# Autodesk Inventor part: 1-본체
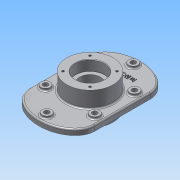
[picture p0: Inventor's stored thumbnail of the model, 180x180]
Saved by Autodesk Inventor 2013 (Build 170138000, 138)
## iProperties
Created: 2015-02
Part Number: 1-본체
Material: 알루미늄 6061
Document SubType Name: Modeling
Designer: Administrator
Mass: 1662.1 g
Surface Area: 942.609 cm^2
Volume: 613.321 cm^3
Density: 2.71 g/cm^3
Author: Administrator
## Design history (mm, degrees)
sketch "스케치1"
  geometry: L1 (70, 60)-(-70, 60); L2 (-70, 60)-(-70, -60); L3 (-70, -60)-(70, -60); L4 (70, -60)-(70, 60); L5 (70, 60)-(-70, -60); L6 (-70, 60)-(70, -60); 7 further points; 2 other entities
  constraints: 12 end point, 6 midpoint, 3 horizontal, 2 parallel, 2 vertical alignment, 1 perpendicular, 8 other
  dimensions: "d0" = 140 distance of L1.start L1.end; "d2" = 120 distance of L3.end L1.start; "d3" = 50 distance from line of L1 point (0, 110); "d4" = 50 distance from line of point (0, -110) L3
extrude "돌출1" new body sketch "스케치1" distance "d5" = 12; taper "d6" = 0 deg
sketch "스케치3"
  geometry: L1 (70, -60)-(70, 60) reference; L2 (-70, 60)-(-70, -60) reference; L3 (53, 60)-(53, -60); L4 (-53, -60)-(-53, 60); C1 r 10 at (53, 42.733); C2 r 10 at (53, -42.733); C3 r 10 at (0, 93); C4 r 10 at (0, -93); C5 r 10 at (-53, 42.733); C6 r 10 at (-53, -42.733); 3 further points; 2 other entities
  constraints: 6 centre point, 5 equal radius, 4 end point, 4 point on line, 3 parallel, 2 vertical alignment, 10 other
  dimensions: "d32" = 17 distance between parallel lines of L1 L3; "d33" = 20 diameter of C1; "d34" = 85.46667 distance of C2.centre C1.centre; "d35" = 42.73333 vertical distance of C2.centre point (0, 0); "d74" = 85.46667 distance of C6.centre C5.centre; "d75" = 42.73333 vertical distance of C6.centre point (0, 0)
extrude "돌출3" join sketch "스케치3" distance "d36" = 5; taper "d37" = 0 deg
hole "구멍3" diameter "d40" = 11; stored, may be unused: countersink angle "d44" = 90 deg, drill point angle "d46" = 0 deg; dims "d38" = 10, "d39" = 10, "d41" = 6, "d42" = 4, "d43" = 2, "d45" = 8
hole "구멍4" diameter "d49" = 11; stored, may be unused: countersink angle "d53" = 90 deg, drill point angle "d55" = 0 deg; dims "d47" = 10, "d48" = 10, "d50" = 6, "d51" = 4, "d52" = 2, "d54" = 8
hole "구멍5" diameter "d58" = 11; stored, may be unused: countersink angle "d62" = 90 deg, drill point angle "d64" = 0 deg; dims "d56" = 10, "d57" = 10, "d59" = 6, "d60" = 4, "d61" = 2, "d63" = 8
hole "구멍6" diameter "d67" = 11; stored, may be unused: countersink angle "d71" = 90 deg, drill point angle "d73" = 0 deg; dims "d65" = 10, "d66" = 10, "d68" = 6, "d69" = 4, "d70" = 2, "d72" = 8
extrude "돌출4" join sketch "스케치3" distance "d76" = 5; taper "d77" = 0 deg
hole "구멍7" diameter "d80" = 11; stored, may be unused: countersink angle "d84" = 90 deg, drill point angle "d86" = 0 deg; dims "d78" = 10, "d79" = 10, "d81" = 6, "d82" = 4, "d83" = 2, "d85" = 8
hole "구멍8" diameter "d89" = 11; stored, may be unused: countersink angle "d93" = 90 deg, drill point angle "d95" = 0 deg; dims "d87" = 10, "d88" = 10, "d90" = 6, "d91" = 4, "d92" = 2, "d94" = 8
node "작업 평면1"
sketch "스케치4"
  geometry: C1 r 50 at (0, 0); 1 further point
  constraints: 1 centre point, 1 coincident
  dimensions: "d97" = 100 diameter of C1
extrude "돌출5" join sketch "스케치4" distance "d99" = 70; taper "d100" = 0 deg
hole "구멍9" diameter "d103" = 45; stored, may be unused: countersink angle "d107" = 90 deg, drill point angle "d109" = 0 deg; dims "d101" = 10, "d102" = 10, "d104" = 6, "d105" = 62, "d106" = 22, "d108" = 8
hole "구멍10" diameter "d112" = 45; stored, may be unused: countersink angle "d116" = 90 deg, drill point angle "d118" = 0 deg; dims "d110" = 10, "d111" = 10, "d113" = 6, "d114" = 62, "d115" = 22, "d117" = 8
sketch "스케치5"
  geometry: C1 r 50 at (0, 0) reference; C2 r 10 at (0, 93) reference; 1 further point
  constraints: 1 vertical alignment, 1 other
  dimensions: "d119" = 65 distance of C1.centre point (0, 65)
feature "엠보싱1" sketch "스케치5" dims "d0" = 140, "d2" = 120, "d3" = 50, "d4" = 50, "d120" = 1, "d121" = 0
sketch "스케치6"
  geometry: C1 r 31 at (0, 0) reference; C2 r 50 at (0, 0) reference; A1 r 41 centre (0, 0) between (-28.991, 28.991) and (28.991, 28.991); 2 further points
  constraints: 4 point on circle, 2 horizontal alignment, 2 vertical alignment, 1 centre point, 1 coincident
  dimensions: "d122" = 82 diameter of A1; "d124" = 90 deg dimension on C1.centre A1.end A1.start
hole "구멍11" sketch "스케치6" at (-28.991, 28.991), (28.991, 28.991), (28.991, -28.991), (-28.991, -28.991) diameter "d126" = 4.917; stored, may be unused: countersink angle "d130" = 90 deg, drill point angle "d132" = 118 deg; dims "d127" = 10, "d128" = 62, "d129" = 22, "d131" = 13
node "작업 평면2"
fillet "모깎기1" dims "d133" = 3
fillet "모깎기2" dims "d134" = 0.3
chamfer "모따기1" distance "d135" = 1; stored, may be unused: second distance "d136" = 2, angle "d137" = 45 deg
node "솔리드1"
mirror "대칭1"
other parameters: "d96" = 23
